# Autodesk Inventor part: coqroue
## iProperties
Shininess: 21.0
Length Units: 11269
Angle Units: 11279
Time Units: 11290
Mass Units: 11283
Length Display Precision: 3
Angle Display Precision: 2
Compacted: True
Created: 2001-12
Part Number: coqroue
Material: Par défaut
Document SubType Name: Modélisation
Designer: pichon
Density: 0.0
Volumn: 0.0
Area: 0.0
PropertySet Name: Model Information
Control State: 0
Master: False
Checked Out: False
Author: pichon
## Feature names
1. Extrusion1
2. Congé2 [Fillet]
3. Révolution1 [Revolution]
4. Extrusion2
5. Coque1
6. Extrusion3
